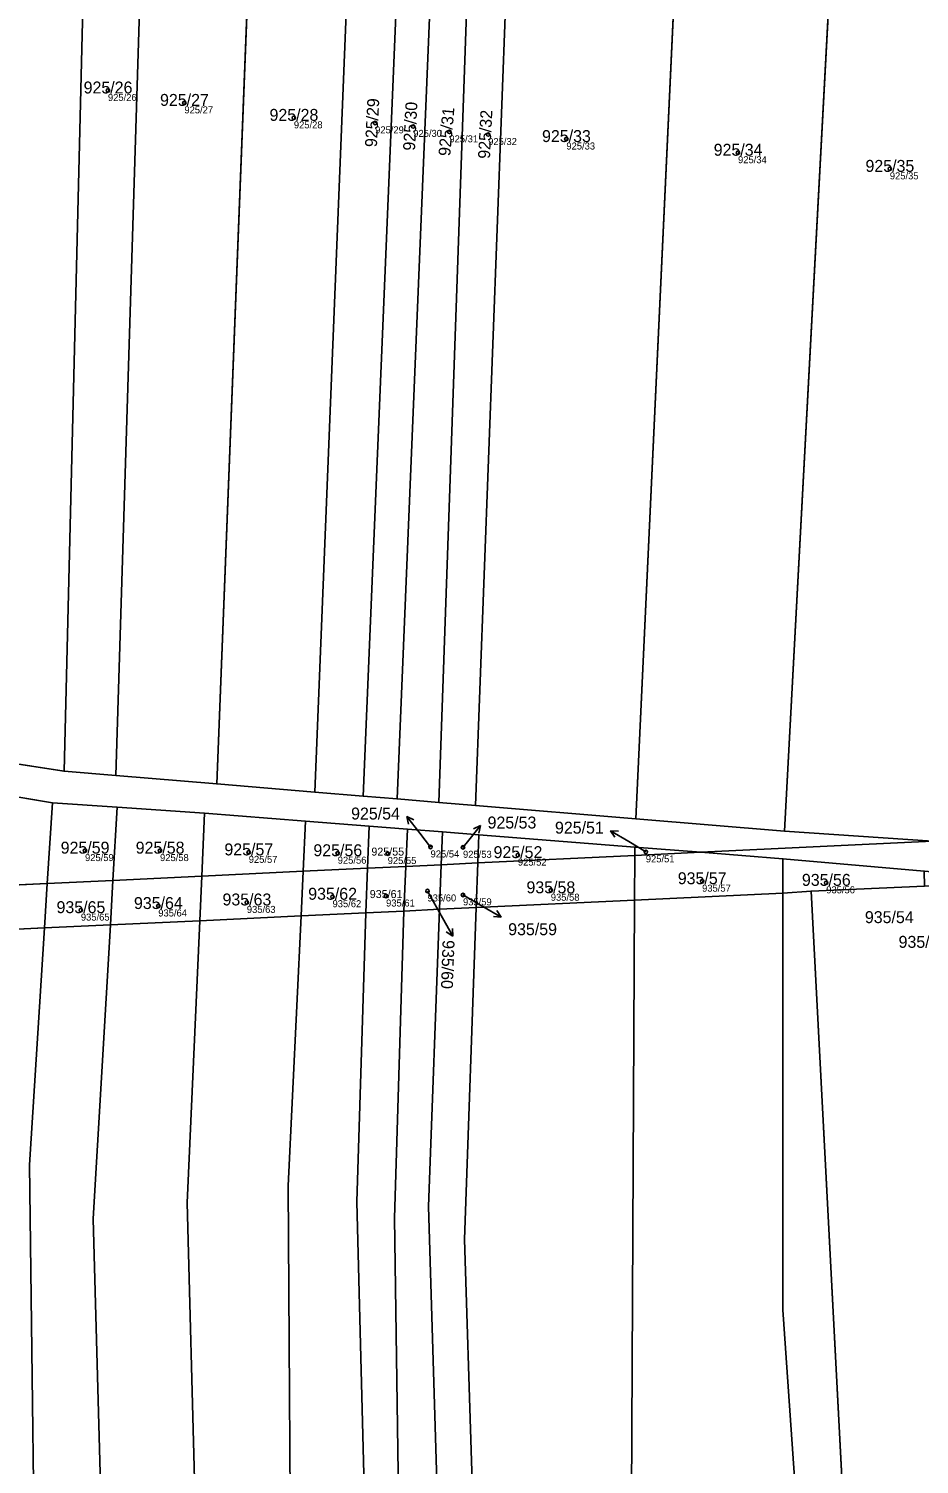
# Model space of a CAD drawing. Extents: x -603967 to -594699, y -1179315 to -1165625.
# Drawn here: x -596507.1 to -596380.2, y -1172437.9 to -1172233.4 of the extents above; entities that cross this region are included whole.
import ezdxf

# ---------------------------------------------------------------- set-up
doc = ezdxf.new("R2010")
doc.units = 0
for name, color, linetype in [('Definiční body', 7, 'Continuous'), ('Hranice parcel', 7, 'Continuous'), ('Parcelní čísla', 7, 'Continuous'), ('Polygon parcely', 7, 'Continuous'), ('Pop  PČ popisy', 7, 'Continuous')]:
    doc.layers.add(name, color=color, linetype=linetype)

msp = doc.modelspace()

# ---------------------------------------------------------------- linework, layer by layer
at = {"layer": 'Definiční body'}
for centre in [(-596495.82, -1172242.17994), (-596484.93, -1172243.94994), (-596469.33, -1172246.07994), (-596457.75, -1172246.79994), (-596452.32, -1172247.29994), (-596447.17, -1172248.07994), (-596441.64, -1172248.45994), (-596430.5, -1172249.09994), (-596406.04, -1172251.04994), (-596384.41, -1172253.34994), (-596499.09, -1172350.47994), (-596488.4, -1172350.47994), (-596475.76, -1172350.72994), (-596463.08, -1172350.84994), (-596455.96, -1172350.89994), (-596449.85, -1172349.95994), (-596445.23, -1172350.00994), (-596437.41, -1172351.11994), (-596419.18, -1172350.65994), (-596411.16, -1172354.83994), (-596393.47, -1172355.06994), (-596463.82, -1172357.04994), (-596456.19, -1172356.94994), (-596450.29, -1172356.22994), (-596445.23, -1172356.78994), (-596432.72, -1172356.12994), (-596499.68, -1172358.95994), (-596488.65, -1172358.36994), (-596476.03, -1172357.85994)]:
    msp.add_circle(centre, 0.25, dxfattribs=at)
at = {"layer": 'Hranice parcel'}
for p, q in [((-596399.43, -1172347.69), (-596382.84, -1172037.54)), ((-596420.62, -1172345.93), (-596406.35, -1172040.08)), ((-596480.31, -1172340.97), (-596468.79, -1172046.83)), ((-596525.15, -1172335.58), (-596502.08, -1172339.16)), ((-596503.74, -1172343.65), (-596525.74, -1172339.98)), ((-596502.08, -1172339.16), (-596494.69, -1172339.77)), ((-596494.69, -1172339.77), (-596480.31, -1172340.97)), ((-596480.31, -1172340.97), (-596466.35, -1172342.13)), ((-596466.35, -1172342.13), (-596459.45, -1172342.7)), ((-596459.45, -1172342.7), (-596454.62, -1172343.1)), ((-596503.74, -1172343.65), (-596504.48, -1172355.17)), ((-596494.5, -1172344.29), (-596503.74, -1172343.65)), ((-596494.5, -1172344.29), (-596495.11, -1172354.72)), ((-596482.06, -1172345.16), (-596494.5, -1172344.29)), ((-596454.62, -1172343.1), (-596448.65, -1172343.6)), ((-596448.65, -1172343.6), (-596443.43, -1172344.03)), ((-596443.43, -1172344.03), (-596420.62, -1172345.93)), ((-596482.06, -1172345.16), (-596482.46, -1172354.11)), ((-596467.67, -1172346.29), (-596482.06, -1172345.16)), ((-596467.67, -1172346.29), (-596468.01, -1172353.42)), ((-596458.6, -1172347), (-596467.67, -1172346.29)), ((-596420.62, -1172345.93), (-596399.43, -1172347.69)), ((-596458.6, -1172347), (-596458.84, -1172352.98)), ((-596453.12, -1172347.43), (-596458.6, -1172347)), ((-596453.12, -1172347.43), (-596453.37, -1172352.72)), ((-596448.15, -1172347.82), (-596453.12, -1172347.43)), ((-596448.15, -1172347.82), (-596448.32, -1172352.48)), ((-596442.97, -1172348.23), (-596448.15, -1172347.82)), ((-596442.97, -1172348.23), (-596443.11, -1172352.23)), ((-596420.74, -1172349.97), (-596442.97, -1172348.23)), ((-596399.43, -1172347.69), (-596378.34, -1172349.13)), ((-596420.74, -1172349.97), (-596420.75, -1172351.16)), ((-596420.75, -1172351.16), (-596411.35, -1172350.71)), ((-596411.35, -1172350.71), (-596420.74, -1172349.97)), ((-596411.35, -1172350.71), (-596378.34, -1172349.13)), ((-596399.65, -1172351.64), (-596411.35, -1172350.71)), ((-596468.01, -1172353.42), (-596458.84, -1172352.98)), ((-596458.84, -1172352.98), (-596459.09, -1172359.34)), ((-596458.84, -1172352.98), (-596453.37, -1172352.72)), ((-596453.37, -1172352.72), (-596453.67, -1172359.08)), ((-596453.37, -1172352.72), (-596448.32, -1172352.48)), ((-596448.32, -1172352.48), (-596448.56, -1172358.84)), ((-596448.32, -1172352.48), (-596443.11, -1172352.23)), ((-596443.11, -1172352.23), (-596443.34, -1172358.59)), ((-596443.11, -1172352.23), (-596420.75, -1172351.16)), ((-596420.75, -1172351.16), (-596420.78, -1172357.52)), ((-596399.65, -1172351.64), (-596399.65, -1172356.52)), ((-596379.5, -1172353.38), (-596399.65, -1172351.64)), ((-596504.48, -1172355.17), (-596495.11, -1172354.72)), ((-596495.11, -1172354.72), (-596495.48, -1172361.06)), ((-596495.11, -1172354.72), (-596482.46, -1172354.11)), ((-596482.46, -1172354.11), (-596482.74, -1172360.46)), ((-596482.46, -1172354.11), (-596468.01, -1172353.42)), ((-596468.01, -1172353.42), (-596468.31, -1172359.78)), ((-596526.25, -1172356.21), (-596504.48, -1172355.17)), ((-596504.48, -1172355.17), (-596504.88, -1172361.5)), ((-596420.78, -1172357.52), (-596399.65, -1172356.52)), ((-596399.65, -1172356.52), (-596395.63, -1172356.23)), ((-596395.63, -1172356.23), (-596379.45, -1172355.56)), ((-596390.52, -1172453.44), (-596395.63, -1172356.23)), ((-596459.09, -1172359.34), (-596453.67, -1172359.08)), ((-596453.67, -1172359.08), (-596448.56, -1172358.84)), ((-596448.56, -1172358.84), (-596443.34, -1172358.59)), ((-596443.34, -1172358.59), (-596420.78, -1172357.52)), ((-596504.88, -1172361.5), (-596495.48, -1172361.06)), ((-596495.48, -1172361.06), (-596482.74, -1172360.46)), ((-596482.74, -1172360.46), (-596468.31, -1172359.78)), ((-596468.31, -1172359.78), (-596459.09, -1172359.34)), ((-596526.45, -1172362.52), (-596504.88, -1172361.5))]:
    msp.add_line(p, q, dxfattribs=at)
for points in [[(-596454.62, -1172343.1), (-596447.98, -1172182.42), (-596443.84, -1172132.82), (-596439.77, -1172043.69)], [(-596448.65, -1172343.6), (-596442.7, -1172172.73), (-596438.88, -1172133.03), (-596434.97, -1172043.17)], [(-596443.43, -1172344.03), (-596438.52, -1172212.57), (-596429, -1172042.53)], [(-596466.35, -1172342.13), (-596459.87, -1172181.54), (-596453.18, -1172045.14)], [(-596459.45, -1172342.7), (-596452.82, -1172183.74), (-596445.27, -1172044.28)], [(-596502.08, -1172339.16), (-596498.32, -1172185.67), (-596492.77, -1172049.42)], [(-596494.69, -1172339.77), (-596488.9, -1172152.4), (-596485.02, -1172048.58)], [(-596385.71, -1172570.49), (-596386.27, -1172567.73), (-596393.08, -1172510.19), (-596399.65, -1172415.89), (-596399.65, -1172356.52)], [(-596423.44, -1172686.22), (-596433.52, -1172647.99), (-596448.24, -1172555.4), (-596453.89, -1172478.78), (-596454.97, -1172402.82), (-596453.67, -1172359.08)], [(-596419.53, -1172681.91), (-596428.56, -1172643.88), (-596443.28, -1172555.09), (-596447.55, -1172487.37), (-596450.13, -1172401.18), (-596448.56, -1172358.84)], [(-596414.92, -1172676.81), (-596422.58, -1172643.52), (-596437.11, -1172558.01), (-596440.02, -1172528.3), (-596443.01, -1172468.96), (-596445.03, -1172405.86), (-596443.34, -1172358.59)], [(-596409.93, -1172574.79), (-596421.26, -1172452.05), (-596420.78, -1172357.52)], [(-596462.82, -1172713.4), (-596473.54, -1172662.83), (-596482.9, -1172612.62), (-596487.05, -1172587.66), (-596494.51, -1172537.35), (-596495.03, -1172508.14), (-596497.93, -1172402.95), (-596495.48, -1172361.06)], [(-596450.03, -1172708.41), (-596459.36, -1172662.7), (-596478.35, -1172554.45), (-596481.26, -1172524.31), (-596484.51, -1172400.66), (-596482.74, -1172360.46)], [(-596436.1, -1172698.46), (-596447.04, -1172658.29), (-596464.52, -1172552.64), (-596466.6, -1172529.3), (-596469.72, -1172464.99), (-596470.13, -1172398.25), (-596468.31, -1172359.78)], [(-596427.48, -1172690.18), (-596438.33, -1172648.35), (-596454.07, -1172555.3), (-596457.49, -1172511.3), (-596460.34, -1172400.52), (-596459.09, -1172359.34)], [(-596472.29, -1172716.99), (-596484.79, -1172663.22), (-596502.93, -1172550.82), (-596506.01, -1172474.56), (-596507.02, -1172395.23), (-596504.88, -1172361.5)]]:
    msp.add_lwpolyline(points, dxfattribs=at)
at = {"layer": 'Polygon parcely'}
for points in [[(-596378.34, -1172349.13), (-596366.55, -1172164.51), (-596359.93, -1172035.06), (-596382.84, -1172037.54), (-596399.43, -1172347.69)], [(-596399.43, -1172347.69), (-596382.84, -1172037.54), (-596406.35, -1172040.08), (-596420.62, -1172345.93)], [(-596420.62, -1172345.93), (-596406.35, -1172040.08), (-596429, -1172042.53), (-596438.52, -1172212.57), (-596443.43, -1172344.03)], [(-596454.62, -1172343.1), (-596447.98, -1172182.42), (-596443.84, -1172132.82), (-596439.77, -1172043.69), (-596445.27, -1172044.28), (-596452.82, -1172183.74), (-596459.45, -1172342.7)], [(-596438.88, -1172133.03), (-596434.97, -1172043.17), (-596439.77, -1172043.69), (-596443.84, -1172132.82), (-596447.98, -1172182.42), (-596454.62, -1172343.1), (-596448.65, -1172343.6), (-596442.7, -1172172.73)], [(-596443.43, -1172344.03), (-596438.52, -1172212.57), (-596429, -1172042.53), (-596434.97, -1172043.17), (-596438.88, -1172133.03), (-596442.7, -1172172.73), (-596448.65, -1172343.6)], [(-596459.87, -1172181.54), (-596453.18, -1172045.14), (-596468.79, -1172046.83), (-596480.31, -1172340.97), (-596466.35, -1172342.13)], [(-596459.45, -1172342.7), (-596452.82, -1172183.74), (-596445.27, -1172044.28), (-596453.18, -1172045.14), (-596459.87, -1172181.54), (-596466.35, -1172342.13)], [(-596480.31, -1172340.97), (-596468.79, -1172046.83), (-596485.02, -1172048.58), (-596488.9, -1172152.4), (-596494.69, -1172339.77)], [(-596502.08, -1172339.16), (-596498.32, -1172185.67), (-596492.77, -1172049.42), (-596516.23, -1172051.95), (-596520.23, -1172152.75), (-596525.15, -1172335.58)], [(-596494.69, -1172339.77), (-596488.9, -1172152.4), (-596485.02, -1172048.58), (-596492.77, -1172049.42), (-596498.32, -1172185.67), (-596502.08, -1172339.16)], [(-596503.74, -1172343.65), (-596525.74, -1172339.98), (-596526.25, -1172356.21), (-596504.48, -1172355.17)], [(-596494.5, -1172344.29), (-596503.74, -1172343.65), (-596504.48, -1172355.17), (-596495.11, -1172354.72)], [(-596482.06, -1172345.16), (-596494.5, -1172344.29), (-596495.11, -1172354.72), (-596482.46, -1172354.11)], [(-596482.46, -1172354.11), (-596468.01, -1172353.42), (-596467.67, -1172346.29), (-596482.06, -1172345.16)], [(-596458.6, -1172347), (-596467.67, -1172346.29), (-596468.01, -1172353.42), (-596458.84, -1172352.98)], [(-596453.12, -1172347.43), (-596458.6, -1172347), (-596458.84, -1172352.98), (-596453.37, -1172352.72)], [(-596448.15, -1172347.82), (-596453.12, -1172347.43), (-596453.37, -1172352.72), (-596448.32, -1172352.48)], [(-596448.32, -1172352.48), (-596443.11, -1172352.23), (-596442.97, -1172348.23), (-596448.15, -1172347.82)], [(-596443.11, -1172352.23), (-596420.75, -1172351.16), (-596420.74, -1172349.97), (-596442.97, -1172348.23)], [(-596420.78, -1172357.52), (-596399.65, -1172356.52), (-596399.65, -1172351.64), (-596411.35, -1172350.71), (-596420.75, -1172351.16)], [(-596411.35, -1172350.71), (-596420.74, -1172349.97), (-596420.75, -1172351.16)], [(-596347.8, -1172351.99), (-596354.62, -1172351.42), (-596362.34, -1172350.78), (-596370.36, -1172349.95), (-596378.34, -1172349.13), (-596411.35, -1172350.71), (-596399.65, -1172351.64), (-596379.5, -1172353.38), (-596371.82, -1172354.05), (-596363.58, -1172354.75), (-596333.14, -1172353.19), (-596339.21, -1172352.7)], [(-596468.31, -1172359.78), (-596459.09, -1172359.34), (-596458.84, -1172352.98), (-596468.01, -1172353.42)], [(-596459.09, -1172359.34), (-596453.67, -1172359.08), (-596453.37, -1172352.72), (-596458.84, -1172352.98)], [(-596453.67, -1172359.08), (-596448.56, -1172358.84), (-596448.32, -1172352.48), (-596453.37, -1172352.72)], [(-596448.56, -1172358.84), (-596443.34, -1172358.59), (-596443.11, -1172352.23), (-596448.32, -1172352.48)], [(-596443.34, -1172358.59), (-596420.78, -1172357.52), (-596420.75, -1172351.16), (-596443.11, -1172352.23)], [(-596379.45, -1172355.56), (-596379.5, -1172353.38), (-596399.65, -1172351.64), (-596399.65, -1172356.52), (-596395.63, -1172356.23)], [(-596504.88, -1172361.5), (-596495.48, -1172361.06), (-596495.11, -1172354.72), (-596504.48, -1172355.17)], [(-596495.48, -1172361.06), (-596482.74, -1172360.46), (-596482.46, -1172354.11), (-596495.11, -1172354.72)], [(-596482.74, -1172360.46), (-596468.31, -1172359.78), (-596468.01, -1172353.42), (-596482.46, -1172354.11)], [(-596356.33, -1172450.42), (-596359.84, -1172410.62), (-596364.57, -1172410.9), (-596366.37, -1172380.25), (-596361.63, -1172379.98), (-596363.58, -1172354.75), (-596371.89, -1172355.14), (-596379.45, -1172355.56), (-596395.63, -1172356.23), (-596390.52, -1172453.44), (-596375.09, -1172452.65), (-596367.01, -1172452.1), (-596360.01, -1172451.45)], [(-596526.45, -1172362.52), (-596504.88, -1172361.5), (-596504.48, -1172355.17), (-596526.25, -1172356.21)], [(-596393.08, -1172510.19), (-596399.65, -1172415.89), (-596399.65, -1172356.52), (-596420.78, -1172357.52), (-596421.26, -1172452.05), (-596409.93, -1172574.79), (-596402.5, -1172573.47), (-596385.71, -1172570.49), (-596386.27, -1172567.73)], [(-596384.26, -1172570.23), (-596390.52, -1172453.44), (-596395.63, -1172356.23), (-596399.65, -1172356.52), (-596399.65, -1172415.89), (-596393.08, -1172510.19), (-596386.27, -1172567.73), (-596385.71, -1172570.49)], [(-596453.89, -1172478.78), (-596454.97, -1172402.82), (-596453.67, -1172359.08), (-596459.09, -1172359.34), (-596460.34, -1172400.52), (-596457.49, -1172511.3), (-596454.07, -1172555.3), (-596438.33, -1172648.35), (-596427.48, -1172690.18), (-596423.63, -1172686.42), (-596423.44, -1172686.22), (-596433.52, -1172647.99), (-596448.24, -1172555.4)], [(-596428.56, -1172643.88), (-596443.28, -1172555.09), (-596447.55, -1172487.37), (-596450.13, -1172401.18), (-596448.56, -1172358.84), (-596453.67, -1172359.08), (-596454.97, -1172402.82), (-596453.89, -1172478.78), (-596448.24, -1172555.4), (-596433.52, -1172647.99), (-596423.44, -1172686.22), (-596419.53, -1172681.91)], [(-596445.03, -1172405.86), (-596443.34, -1172358.59), (-596448.56, -1172358.84), (-596450.13, -1172401.18), (-596447.55, -1172487.37), (-596443.28, -1172555.09), (-596428.56, -1172643.88), (-596419.53, -1172681.91), (-596415.94, -1172677.97), (-596414.92, -1172676.81), (-596422.58, -1172643.52), (-596437.11, -1172558.01), (-596440.02, -1172528.3), (-596443.01, -1172468.96)], [(-596420.78, -1172357.52), (-596443.34, -1172358.59), (-596445.03, -1172405.86), (-596443.01, -1172468.96), (-596440.02, -1172528.3), (-596437.11, -1172558.01), (-596422.58, -1172643.52), (-596414.92, -1172676.81), (-596412.17, -1172673.68), (-596403.98, -1172663.03), (-596395.8, -1172653.78), (-596409.93, -1172574.79), (-596421.26, -1172452.05)], [(-596482.9, -1172612.62), (-596487.05, -1172587.66), (-596494.51, -1172537.35), (-596495.03, -1172508.14), (-596497.93, -1172402.95), (-596495.48, -1172361.06), (-596504.88, -1172361.5), (-596507.02, -1172395.23), (-596506.01, -1172474.56), (-596502.93, -1172550.82), (-596484.79, -1172663.22), (-596472.29, -1172716.99), (-596465.3, -1172714.27), (-596462.82, -1172713.4), (-596473.54, -1172662.83)], [(-596450.03, -1172708.41), (-596459.36, -1172662.7), (-596478.35, -1172554.45), (-596481.26, -1172524.31), (-596484.51, -1172400.66), (-596482.74, -1172360.46), (-596495.48, -1172361.06), (-596497.93, -1172402.95), (-596495.03, -1172508.14), (-596494.51, -1172537.35), (-596487.05, -1172587.66), (-596482.9, -1172612.62), (-596473.54, -1172662.83), (-596462.82, -1172713.4), (-596454.6, -1172710.51)], [(-596447.04, -1172658.29), (-596464.52, -1172552.64), (-596466.6, -1172529.3), (-596469.72, -1172464.99), (-596470.13, -1172398.25), (-596468.31, -1172359.78), (-596482.74, -1172360.46), (-596484.51, -1172400.66), (-596481.26, -1172524.31), (-596478.35, -1172554.45), (-596459.36, -1172662.7), (-596450.03, -1172708.41), (-596447.97, -1172707.46), (-596439.75, -1172701.8), (-596436.1, -1172698.46)], [(-596438.33, -1172648.35), (-596454.07, -1172555.3), (-596457.49, -1172511.3), (-596460.34, -1172400.52), (-596459.09, -1172359.34), (-596468.31, -1172359.78), (-596470.13, -1172398.25), (-596469.72, -1172464.99), (-596466.6, -1172529.3), (-596464.52, -1172552.64), (-596447.04, -1172658.29), (-596436.1, -1172698.46), (-596433.67, -1172696.23), (-596427.48, -1172690.18)], [(-596484.79, -1172663.22), (-596502.93, -1172550.82), (-596506.01, -1172474.56), (-596507.02, -1172395.23), (-596504.88, -1172361.5), (-596526.45, -1172362.52), (-596529.06, -1172427.99), (-596529.53, -1172495.15), (-596526.79, -1172548.51), (-596518.9, -1172600.41), (-596508.96, -1172660.81), (-596494.11, -1172724.23), (-596476.11, -1172718.48), (-596472.29, -1172716.99)]]:
    msp.add_lwpolyline(points, close=True, dxfattribs=at)
msp.add_lwpolyline([(-596525.74, -1172339.98), (-596503.74, -1172343.65), (-596494.5, -1172344.29), (-596482.06, -1172345.16), (-596467.67, -1172346.29), (-596458.6, -1172347), (-596453.12, -1172347.43), (-596448.15, -1172347.82), (-596442.97, -1172348.23), (-596420.74, -1172349.97), (-596411.35, -1172350.71), (-596378.34, -1172349.13), (-596399.43, -1172347.69), (-596420.62, -1172345.93), (-596443.43, -1172344.03), (-596448.65, -1172343.6), (-596454.62, -1172343.1), (-596459.45, -1172342.7), (-596466.35, -1172342.13), (-596480.31, -1172340.97), (-596494.69, -1172339.77), (-596502.08, -1172339.16), (-596525.15, -1172335.58)], dxfattribs=at)
at = {"layer": 'Pop  PČ popisy'}
for p, q in [((-596451.39, -1172347.98), (-596453.238, -1172345.615)), ((-596453.238, -1172345.615), (-596452.226, -1172346.096)), ((-596453.238, -1172345.615), (-596453.016, -1172346.713)), ((-596444.61, -1172349.24), (-596442.721, -1172346.908)), ((-596442.721, -1172346.908), (-596443.741, -1172347.371)), ((-596442.721, -1172346.908), (-596442.963, -1172348.001)), ((-596449.85, -1172349.96), (-596451.39, -1172347.98)), ((-596421.62, -1172349.18), (-596424.192, -1172347.634)), ((-596424.192, -1172347.634), (-596423.076, -1172347.721)), ((-596424.192, -1172347.634), (-596423.592, -1172348.579)), ((-596445.23, -1172350.01), (-596444.61, -1172349.24)), ((-596419.18, -1172350.66), (-596421.62, -1172349.18)), ((-596450.29, -1172356.23), (-596448.15, -1172360.06)), ((-596445.23, -1172356.79), (-596442.38, -1172358.45)), ((-596442.38, -1172358.45), (-596439.781, -1172359.95)), ((-596439.781, -1172359.95), (-596440.398, -1172359.016)), ((-596448.15, -1172360.06), (-596446.695, -1172362.685)), ((-596439.781, -1172359.95), (-596440.899, -1172359.883)), ((-596446.695, -1172362.685), (-596447.619, -1172362.052)), ((-596446.695, -1172362.685), (-596446.743, -1172361.566))]:
    msp.add_line(p, q, dxfattribs=at)

# ---------------------------------------------------------------- texts
at = {"layer": 'Definiční body'}
for s, p in [('925/26', (-596495.82, -1172243.669)), ('925/27', (-596484.93, -1172245.439)), ('925/28', (-596469.33, -1172247.569)), ('925/29', (-596457.75, -1172248.289)), ('925/30', (-596452.32, -1172248.789)), ('925/31', (-596447.17, -1172249.569)), ('925/32', (-596441.64, -1172249.949)), ('925/33', (-596430.5, -1172250.589)), ('925/34', (-596406.04, -1172252.539)), ('925/35', (-596384.41, -1172254.839)), ('925/59', (-596499.09, -1172351.969)), ('925/58', (-596488.4, -1172351.969)), ('925/54', (-596449.85, -1172351.449)), ('925/53', (-596445.23, -1172351.499)), ('925/57', (-596475.76, -1172352.219)), ('925/56', (-596463.08, -1172352.339)), ('925/55', (-596455.96, -1172352.389)), ('925/52', (-596437.41, -1172352.609)), ('925/51', (-596419.18, -1172352.149)), ('935/60', (-596450.29, -1172357.719)), ('935/58', (-596432.72, -1172357.619)), ('935/57', (-596411.16, -1172356.329)), ('935/56', (-596393.47, -1172356.559)), ('935/64', (-596488.65, -1172359.859)), ('935/63', (-596476.03, -1172359.349)), ('935/62', (-596463.82, -1172358.539)), ('935/61', (-596456.19, -1172358.439)), ('935/59', (-596445.23, -1172358.279)), ('935/65', (-596499.68, -1172360.449))]:
    msp.add_text(s, height=0.999996, dxfattribs=at).set_placement(p)
at = {"layer": 'Parcelní čísla'}
for s, height, p in [('925/26', 1.699998, (-596499.286, -1172242.605)), ('925/27', 1.699998, (-596488.396, -1172244.375)), ('925/28', 1.699998, (-596472.796, -1172246.505)), ('925/33', 1.699998, (-596433.966, -1172249.525)), ('925/34', 1.699998, (-596409.506, -1172251.475)), ('925/35', 1.699998, (-596387.876, -1172253.775)), ('925/54', 1.699998, (-596461.172, -1172346.045)), ('925/53', 1.699998, (-596441.73, -1172347.325)), ('925/51', 1.699998, (-596432.122, -1172348.055)), ('925/59', 1.699998, (-596502.556, -1172350.905)), ('925/58', 1.699998, (-596491.866, -1172350.905)), ('925/57', 1.699998, (-596479.226, -1172351.155)), ('925/56', 1.699998, (-596466.546, -1172351.275)), ('925/55', 1.14, (-596458.284, -1172351.185)), ('925/52', 1.699998, (-596440.876, -1172351.545)), ('935/58', 1.699998, (-596436.186, -1172356.555)), ('935/57', 1.699998, (-596414.626, -1172355.265)), ('935/56', 1.699998, (-596396.936, -1172355.495)), ('935/64', 1.699998, (-596492.116, -1172358.795)), ('935/63', 1.699998, (-596479.496, -1172358.285)), ('935/62', 1.699998, (-596467.286, -1172357.475)), ('935/61', 1.14, (-596458.514, -1172357.235)), ('935/65', 1.699998, (-596503.146, -1172359.385)), ('935/54', 1.699998, (-596387.962, -1172360.805)), ('935/59', 1.699998, (-596438.79, -1172362.525)), ('935/55', 1.699998, (-596383.162, -1172364.325))]:
    msp.add_text(s, height=height, dxfattribs=at).set_placement(p)
for s, rotation, p in [('925/29', 87, (-596457.507, -1172250.283)), ('925/30', 87, (-596452.077, -1172250.783)), ('925/31', 85, (-596447.048, -1172251.57)), ('925/32', 87, (-596441.397, -1172251.943)), ('935/60', 267.9999972, (-596448.133, -1172363.2))]:
    msp.add_text(s, height=1.699998, rotation=rotation, dxfattribs=at).set_placement(p)

doc.saveas('drawing.dxf')
